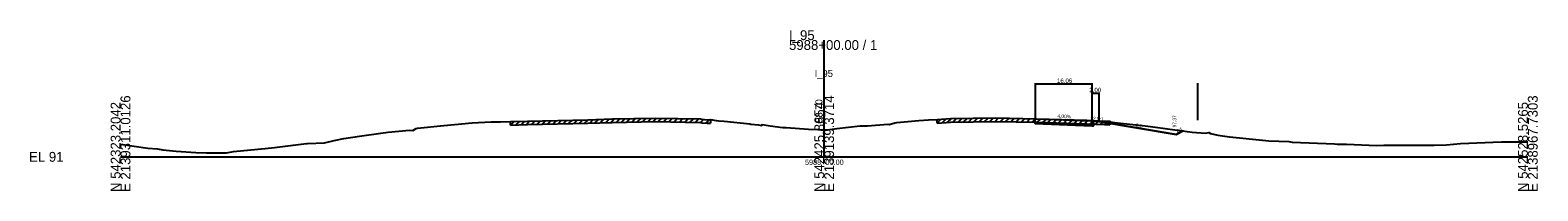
# Model space of a CAD drawing. Extents: x -12534 to 3403, y -1332 to 21983.
# Drawn here: x -25.7 to 402.8, y 17490.3 to 17536.1 of the extents above; entities that cross this region are included whole.
import ezdxf

# ---------------------------------------------------------------- set-up
doc = ezdxf.new("R2010")
doc.units = 0
for name, color, linetype in [('RD_GPK_XS_Cell', 7, 'Continuous'), ('RD_XD_TX_Width', 7, 'Continuous'), ('RD_XS_Base', 7, 'Continuous'), ('RD_XS_EarthShd', 7, 'Continuous'), ('RD_XS_EwShp', 7, 'Continuous'), ('RD_XS_ExGround', 7, 'Continuous'), ('RD_XS_ExPaveRet', 7, 'Continuous'), ('RD_XS_OSBase', 7, 'Continuous'), ('RD_XS_Pave', 7, 'Continuous'), ('RD_XS_TieSlope', 7, 'Continuous'), ('RD_XS_TX_Baseline', 7, 'Continuous'), ('RD_XS_TX_Elev_EX', 7, 'Continuous'), ('RD_XS_TX_Elev_PR', 7, 'Continuous'), ('RD_XS_TX_ShdSlope', 7, 'Continuous'), ('RD_XS_TX_Slope', 7, 'Continuous'), ('RD_XS_TX_Station', 7, 'Continuous')]:
    doc.layers.add(name, color=color, linetype=linetype)

msp = doc.modelspace()

# ---------------------------------------------------------------- linework, layer by layer
at = {"layer": 'RD_GPK_XS_Cell'}
for p, q in [((200, 17500), (200, 17533.22)), ((0, 17500), (200, 17500)), ((200, 17500), (400, 17500))]:
    msp.add_line(p, q, dxfattribs=at)
at = {"layer": 'RD_XD_TX_Width'}
for p, q in [((260, 17520.99), (260, 17511.04)), ((260, 17520.79), (276.06, 17520.79)), ((276.06, 17520.99), (276.06, 17510.4)), ((306.06, 17520.99), (306.06, 17510.4)), ((276.06, 17518.35), (276.06, 17510.4)), ((276.06, 17518.15), (278.06, 17518.15)), ((278.06, 17518.35), (278.06, 17510.24))]:
    msp.add_line(p, q, dxfattribs=at)
at = {"layer": 'RD_XS_Base'}
msp.add_line((260, 17509.44), (276.06, 17508.8), dxfattribs=at)
at = {"layer": 'RD_XS_EarthShd'}
msp.add_line((276.06, 17510.2), (278.06, 17510.04), dxfattribs=at)
at = {"layer": 'RD_XS_EwShp'}
msp.add_lwpolyline([(299.63, 17507.7), (302.06, 17507.37), (300.06, 17506.37), (278.06, 17510.04), (276.06, 17510.2), (276.06, 17509.8), (276.56, 17509.78), (276.56, 17508.78), (276.06, 17508.8), (260, 17509.44), (260, 17510.44), (260, 17510.84), (260.32, 17510.83), (274.65, 17510.43), (279.66, 17510.19), (279.94, 17510.17), (281.15, 17510.12), (281.15, 17509.98), (283.4, 17509.7), (291.2, 17508.78), (294.17, 17508.41)], close=True, dxfattribs=at)
at = {"layer": 'RD_XS_ExGround'}
msp.add_lwpolyline([(0, 17503.57), (7.79, 17502.49), (10.47, 17502.25), (12.05, 17501.97), (15.84, 17501.65), (21.42, 17501.25), (24.42, 17501.17), (30.07, 17501.15), (32.11, 17501.51), (39.04, 17502.17), (41.1, 17502.34), (43.8, 17502.64), (49.1, 17503.32), (52.82, 17503.78), (53.13, 17503.77), (57.98, 17503.96), (60.67, 17504.68), (63.47, 17505.21), (67.93, 17505.87), (73.99, 17506.77), (76.03, 17507.04), (82.14, 17507.58), (83.03, 17507.53), (84.07, 17508.08), (84.4, 17508.15), (91.88, 17508.93), (94.95, 17509.21), (99.93, 17509.63), (105.37, 17509.94), (107.97, 17509.98), (110.85, 17510.01), (115.67, 17510.18), (132.86, 17510.57), (139.77, 17510.78), (152.05, 17511.03), (164.87, 17510.77), (165.19, 17510.7), (166.77, 17510.56), (167.65, 17510.58), (169.27, 17510.36), (170.08, 17510.25), (171.53, 17510.13), (178.82, 17509.36), (179.14, 17509.34), (181.35, 17509.12), (182.22, 17508.95), (182.4, 17509.16), (184.67, 17508.81), (188.21, 17508.38), (189.17, 17508.3), (195.56, 17507.89), (198.16, 17507.79), (199.06, 17507.69), (200, 17507.7), (200.98, 17507.71), (203.57, 17508.03), (210.22, 17508.79), (212.31, 17508.86), (218.12, 17509.33), (218.49, 17509.2), (220.04, 17509.64), (220.67, 17509.75), (226.85, 17510.3), (229.69, 17510.53), (232.07, 17510.6), (235.93, 17510.88), (248.75, 17511.07), (260.32, 17510.83), (274.65, 17510.43), (279.66, 17510.19), (279.94, 17510.17), (281.15, 17510.12), (281.15, 17509.98), (283.4, 17509.7), (291.2, 17508.78), (294.17, 17508.41), (299.63, 17507.7), (304.6, 17507.02), (308.37, 17506.73), (309.37, 17506.88), (309.76, 17506.64), (311.84, 17506.12), (315.16, 17505.68), (325.55, 17504.61), (326.36, 17504.55), (332.08, 17504.34), (332.99, 17504.17), (345.08, 17503.7), (345.81, 17503.65), (346.62, 17503.62), (348.42, 17503.59), (354.91, 17503.3), (356.96, 17503.26), (359.08, 17503.35), (373.41, 17503.33), (376.88, 17503.46), (380.9, 17503.83), (392.48, 17504.27), (400, 17504.27)], dxfattribs=at)
at = {"layer": 'RD_XS_ExPaveRet'}
for p, q in [((110.85, 17509.01), (111.88, 17510.05)), ((110.85, 17509.01), (110.85, 17510.01)), ((112.35, 17509.07), (113.38, 17510.1)), ((113.85, 17509.12), (114.88, 17510.16)), ((115.35, 17509.17), (116.37, 17510.2)), ((116.85, 17509.21), (117.87, 17510.23)), ((118.35, 17509.24), (119.37, 17510.27)), ((119.85, 17509.28), (120.87, 17510.3)), ((121.35, 17509.31), (122.37, 17510.33)), ((122.85, 17509.34), (123.87, 17510.37)), ((124.35, 17509.38), (125.37, 17510.4)), ((125.85, 17509.41), (126.87, 17510.43)), ((127.35, 17509.45), (128.37, 17510.47)), ((128.85, 17509.48), (129.87, 17510.5)), ((130.35, 17509.51), (131.37, 17510.54)), ((131.85, 17509.55), (132.87, 17510.57)), ((133.35, 17509.58), (134.38, 17510.61)), ((134.85, 17509.63), (135.88, 17510.66)), ((136.35, 17509.67), (137.38, 17510.7)), ((137.85, 17509.72), (138.88, 17510.75)), ((139.35, 17509.76), (140.37, 17510.79)), ((139.77, 17509.78), (152.05, 17510.03)), ((140.85, 17509.8), (141.87, 17510.82)), ((142.35, 17509.83), (143.37, 17510.85)), ((143.85, 17509.86), (144.87, 17510.88)), ((145.35, 17509.89), (146.37, 17510.91)), ((146.85, 17509.92), (147.87, 17510.94)), ((148.35, 17509.95), (149.37, 17510.97)), ((149.85, 17509.98), (150.87, 17511)), ((151.35, 17510.01), (152.35, 17511.02)), ((152.05, 17510.03), (164.87, 17509.77)), ((152.85, 17510.01), (153.83, 17510.99)), ((154.35, 17509.98), (155.33, 17510.96)), ((155.85, 17509.95), (156.83, 17510.93)), ((157.35, 17509.92), (158.33, 17510.9)), ((158.85, 17509.89), (159.83, 17510.87)), ((160.35, 17509.86), (161.33, 17510.84)), ((161.85, 17509.83), (162.83, 17510.81)), ((163.35, 17509.8), (164.33, 17510.78)), ((164.85, 17509.77), (165.73, 17510.65)), ((166.35, 17509.6), (167.32, 17510.57)), ((167.65, 17510.58), (167.65, 17509.58)), ((232.07, 17509.6), (233.15, 17510.68)), ((232.07, 17509.6), (232.07, 17510.6)), ((232.07, 17509.6), (235.93, 17509.88)), ((233.57, 17509.71), (234.65, 17510.79)), ((235.07, 17509.82), (236.14, 17510.88)), ((235.93, 17509.88), (248.75, 17510.07)), ((236.57, 17509.89), (237.59, 17510.91)), ((238.07, 17509.91), (239.09, 17510.93)), ((239.57, 17509.94), (240.59, 17510.95)), ((241.07, 17509.96), (242.09, 17510.97)), ((242.57, 17509.98), (243.59, 17511)), ((244.07, 17510), (245.09, 17511.02)), ((245.57, 17510.03), (246.59, 17511.04)), ((247.07, 17510.05), (248.09, 17511.06)), ((248.57, 17510.07), (249.56, 17511.06)), ((248.75, 17510.07), (260.32, 17509.83)), ((250.07, 17510.05), (251.05, 17511.03)), ((251.57, 17510.01), (252.55, 17510.99)), ((253.07, 17509.98), (254.05, 17510.96)), ((254.57, 17509.95), (255.55, 17510.93)), ((256.07, 17509.92), (257.05, 17510.9)), ((257.57, 17509.89), (258.55, 17510.87)), ((259.07, 17509.86), (260.05, 17510.84)), ((260.57, 17509.82), (261.55, 17510.8)), ((262.07, 17509.78), (263.05, 17510.76)), ((263.57, 17509.74), (264.55, 17510.71)), ((265.07, 17509.7), (266.05, 17510.67)), ((266.57, 17509.66), (267.55, 17510.63)), ((268.07, 17509.62), (269.05, 17510.59)), ((269.57, 17509.58), (270.55, 17510.55)), ((271.07, 17509.53), (272.05, 17510.51)), ((272.57, 17509.49), (273.55, 17510.47)), ((274.07, 17509.45), (275.04, 17510.42)), ((275.57, 17509.39), (276.53, 17510.34)), ((277.07, 17509.32), (278.03, 17510.27)), ((278.57, 17509.25), (279.53, 17510.2)), ((280.07, 17509.17), (281.03, 17510.12)), ((281.15, 17510.12), (281.15, 17509.12)), ((110.85, 17509.01), (115.67, 17509.18)), ((115.67, 17509.18), (132.86, 17509.57)), ((132.86, 17509.57), (139.77, 17509.78)), ((164.87, 17509.77), (165.19, 17509.7)), ((165.19, 17509.7), (166.77, 17509.56)), ((166.77, 17509.56), (167.65, 17509.58)), ((260.32, 17509.83), (274.65, 17509.43)), ((274.65, 17509.43), (279.66, 17509.19)), ((279.66, 17509.19), (279.94, 17509.17)), ((279.94, 17509.17), (281.15, 17509.12))]:
    msp.add_line(p, q, dxfattribs=at)
at = {"layer": 'RD_XS_OSBase'}
for p, q in [((260, 17510.44), (260, 17510.84)), ((260, 17509.44), (260, 17510.44)), ((276.06, 17509.8), (276.06, 17510.2)), ((276.56, 17509.78), (276.06, 17509.8)), ((276.06, 17508.8), (276.56, 17508.78)), ((276.56, 17508.78), (276.56, 17509.78))]:
    msp.add_line(p, q, dxfattribs=at)
at = {"layer": 'RD_XS_Pave'}
msp.add_line((260, 17510.84), (276.06, 17510.2), dxfattribs=at)
at = {"layer": 'RD_XS_TieSlope'}
for p, q in [((278.06, 17510.04), (300.06, 17506.37)), ((300.06, 17506.37), (302.06, 17507.37))]:
    msp.add_line(p, q, dxfattribs=at)

# ---------------------------------------------------------------- texts
at = {"layer": 'RD_GPK_XS_Cell'}
for s, p in [('I_95', (190, 17533.22)), ('5988+00.00 / 1', (190, 17530.42)), ('EL 91', (-26, 17498.6))]:
    msp.add_text(s, height=2.8, dxfattribs=at).set_placement(p)
for s, p in [('N 542323.2042', (0, 17490)), ('E 2139311.0126', (2.8, 17490)), ('N 542425.8654', (200, 17490)), ('E 2139139.3714', (202.8, 17490)), ('N 542528.5265', (400, 17490)), ('E 2138967.7303', (402.8, 17490))]:
    msp.add_text(s, height=2.8, rotation=90, dxfattribs=at).set_placement(p)
at = {"layer": 'RD_XD_TX_Width'}
for s, p in [('16.06', (266.17, 17521.04)), ('2.00', (275.37, 17518.4))]:
    msp.add_text(s, height=1.25, dxfattribs=at).set_placement(p)
at = {"layer": 'RD_XS_TX_Baseline'}
msp.add_text('I_95', height=2, dxfattribs=at).set_placement((197.28, 17522.7))
at = {"layer": 'RD_XS_TX_Elev_EX'}
msp.add_text('98.70', height=2, rotation=90, dxfattribs=at).set_placement((199.5, 17509.7))
at = {"layer": 'RD_XS_TX_Elev_PR'}
msp.add_text('97.37', height=1, rotation=90, dxfattribs=at).set_placement((300.06, 17508.37))
at = {"layer": 'RD_XS_TX_ShdSlope'}
msp.add_text('12.5:1', height=1, rotation=355.4261, dxfattribs=at).set_placement((275.57, 17510.49))
msp.add_text('12.5:1', height=1, rotation=355.4261, dxfattribs=at).set_placement((275.57, 17510.49))
at = {"layer": 'RD_XS_TX_Slope'}
for s, rotation, p in [('4.00%', 357.7094, (266.25, 17511.09)), ('6:1', 350.5377, (288.41, 17508.56)), ('2:1', 26.5651, (300.27, 17506.76))]:
    msp.add_text(s, height=1, rotation=rotation, dxfattribs=at).set_placement(p)
at = {"layer": 'RD_XS_TX_Station'}
msp.add_text('5988+00.00', height=1.5, dxfattribs=at).set_placement((194.54, 17497.7))

doc.saveas('drawing.dxf')
